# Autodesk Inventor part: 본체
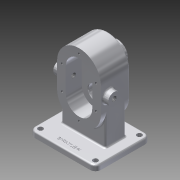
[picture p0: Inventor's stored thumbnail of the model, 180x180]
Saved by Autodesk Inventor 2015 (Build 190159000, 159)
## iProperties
Created: 2020-09
Part Number: 본체
Material: 알루미늄 6061
Document SubType Name: Modeling
Designer: Administrator
Density: 2.7 g/cm^3
Appearance: 알루미늄 - 평지
Mass: 1440.46 g
Surface Area: 785.636 cm^2
Volume: 533.505 cm^3
Author: Administrator
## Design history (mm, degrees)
sketch "스케치1"
  geometry: L1 (40, 0)-(40, 44); L2 (-40, 44)-(-40, 0); A1 r 40 centre (0, 0) between (-40, 0) and (40, 0); A2 r 40 centre (0, 44) between (40, 44) and (-40, 44); 1 further point
  constraints: 4 end point, 4 point on circle, 4 tangent, 2 centre point, 1 coincident, 1 parallel, 1 vertical
  dimensions: "d10" = 44 distance of L1.end L1.start; "d121" = 40 radius of A2
extrude "돌출1" new body sketch "스케치1" stored distance "d11" = 53; taper "d12" = 0 deg
sketch "스케치2"
  geometry: L1 (0, 0)-(0, 44); L2 (0, 0)-(0, 44); L3 (24, 0)-(24, 44); L4 (-24, 44)-(-24, 0); A1 r 24 centre (0, 0) between (-24, 0) and (24, 0); A2 r 24 centre (0, 44) between (24, 44) and (-24, 44); 1 further point
  constraints: 10 end point, 4 point on circle, 4 tangent, 2 centre point, 2 vertical, 1 midpoint, 1 parallel
  dimensions: "d13" = 44 distance of L1.start L1.end; "d14" = 48 diameter of A2
extrude "돌출2" cut sketch "스케치2" distance "d15" = 29; taper "d16" = 0 deg
sketch "스케치3"
  geometry: C1 r 19 at (0, 44); A1 r 40 centre (0, 44) between (40, 44) and (-40, 44) reference; 1 further point
  constraints: 1 centre point, 1 coincident
  dimensions: "d17" = 38 diameter of C1
extrude "돌출3" join sketch "스케치3" distance "d18" = 17; taper "d19" = 0 deg
sketch "스케치4"
  geometry: C1 r 19 at (0, 0) reference; C2 r 14 at (0, 0); 1 further point
  constraints: 1 centre point, 1 coincident
  dimensions: "d20" = 28 diameter of C2
extrude "돌출4" cut sketch "스케치4" distance "d21" = 7.3; taper "d22" = 0 deg
sketch "스케치5"
  geometry: C1 r 12.5 at (0, 44); A1 r 24 centre (0, 44) between (24, 44) and (-24, 44) reference; 1 further point
  constraints: 1 centre point, 1 coincident
  dimensions: "d23" = 25 diameter of C1
extrude "돌출5" cut sketch "스케치5" distance "d24" = 15; taper "d25" = 0 deg
sketch "스케치6"
  geometry: C1 r 12.5 at (0, 0) reference; C2 r 8.5 at (0, 0); 1 further point
  constraints: 1 centre point, 1 coincident
  dimensions: "d26" = 17 diameter of C2
extrude "돌출6" cut sketch "스케치6" distance "d27" = 20; taper "d28" = 0 deg
fillet "모깎기1" dims "d29" = 0.5
chamfer "모따기1" distance "d30" = 0.7; stored, may be unused: second distance "d31" = 2, angle "d32" = 30 deg
sketch "스케치7"
  geometry: C1 r 12.5 at (0, 0); A1 r 24 centre (0, 0) between (-24, 0) and (24, 0) reference; 1 further point
  constraints: 1 centre point, 1 coincident
  dimensions: "d33" = 25 diameter of C1
extrude "돌출7" cut sketch "스케치7" distance "d34" = 15; taper "d35" = 0 deg
chamfer "모따기2" distance "d36" = 1; stored, may be unused: second distance "d37" = 2, angle "d38" = 45 deg
sketch "스케치8"
  geometry: L1 (0, 0)-(0, 22); L2 (0, 44)-(0, 0) reference; L3 (0, 22)-(14, 22); C1 r 11 at (14, 22); 1 further point
  constraints: 4 end point, 1 centre point, 1 coincident, 1 horizontal, 1 midpoint
  dimensions: "d43" = 22 distance of L1.start L1.end (derived); "d44" = 14 distance of L1.end L3.end; "d45" = 22 diameter of C1
extrude "돌출8" join sketch "스케치8" distance "d46" = 10; taper "d47" = 0 deg
sketch "스케치9"
  geometry: L1 (0, 0)-(0, 22); L2 (0, 0)-(0, 44) reference; L3 (0, 22)-(-14, 22); C1 r 11 at (-14, 22); 1 further point
  constraints: 4 end point, 1 centre point, 1 coincident, 1 midpoint, 1 perpendicular
  dimensions: "d48" = 22 distance of L1.start L1.end (derived); "d49" = 14 distance of L1.end L3.end; "d50" = 22 diameter of C1
extrude "돌출9" join sketch "스케치9" distance "d51" = 10; taper "d52" = 0 deg
sketch "스케치10"
  geometry: C1 r 11 at (0, 0) reference; 1 further point
sketch "스케치11"
  geometry: C1 r 11 at (0, 0) reference; 1 further point
hole "구멍1" sketch "스케치11" at (0, 0) diameter "d53" = 8.376; stored, may be unused: countersink angle "d57" = 90 deg, drill point angle "d59" = 118 deg; dims "d54" = 26, "d55" = 4, "d56" = 2, "d58" = 30
hole "구멍2" sketch "스케치10" diameter "d60" = 8.376; stored, may be unused: countersink angle "d64" = 90 deg, drill point angle "d66" = 118 deg; dims "d61" = 26, "d62" = 4, "d63" = 2, "d65" = 30
fillet "모깎기2" dims "d67" = 3
sketch "스케치12"
  geometry: L1 (0, 44)-(0, 75); L2 (0, 44)-(-31, 44); L3 (0, 44)-(31, 44); C1 r 13.5 at (0, 44) reference; C2 r 2.828 at (0, 75); C3 r 2.236 at (31, 44); C4 r 2.236 at (-31, 44); A1 r 31 centre (0, 44) between (0, 75) and (-31, 44); 1 further point
  constraints: 6 end point, 4 centre point, 4 coincident, 3 point on circle, 2 horizontal, 1 vertical
  dimensions: "d68" = 62 diameter of A1; "d69" = 5.65685 diameter of C2; "d70" = 4.47214 diameter of C4; "d71" = 4.47214 diameter of C3
hole "구멍3" sketch "스케치12" at (0, 75), (31, 44), (-31, 44) diameter "d72" = 4.134; stored, may be unused: countersink angle "d76" = 90 deg, drill point angle "d78" = 118 deg; dims "d73" = 10, "d74" = 4, "d75" = 2, "d77" = 12
sketch "스케치13"
  geometry: L1 (0, 0)-(0, -31); L2 (0, 0)-(-31, 0); L3 (0, 0)-(31, 0); C1 r 13.5 at (0, 0) reference; C2 r 2.828 at (31, 0); C3 r 2.828 at (0, -31); C4 r 3.464 at (-31, 0); A1 r 31 centre (0, 0) between (0, -31) and (-31, 0); 1 further point
  constraints: 6 end point, 4 centre point, 4 coincident, 3 point on circle, 1 horizontal, 1 point on line, 1 vertical
  dimensions: "d79" = 62 diameter of A1; "d80" = 6.9282 diameter of C4; "d81" = 5.65685 diameter of C3; "d82" = 5.65685 diameter of C2
hole "구멍4" sketch "스케치13" at (31, 0), (-31, 0), (0, -31) diameter "d83" = 4.134; stored, may be unused: countersink angle "d87" = 90 deg, drill point angle "d89" = 118 deg; dims "d84" = 10, "d85" = 4, "d86" = 2, "d88" = 12
fillet "모깎기3" dims "d90" = 3
node "작업 평면1"
sketch "스케치15"
  geometry: L1 (0, 0)-(0, -43.5); L2 (0, 0)-(0, 56.5); L3 (0, 56.5)-(60, 56.5); L4 (60, 56.5)-(60, -43.5); L5 (60, -43.5)-(-60, -43.5); L6 (-60, -43.5)-(-60, 56.5); L7 (-60, 56.5)-(0, 56.5)
  constraints: 14 end point, 2 perpendicular, 2 vertical, 1 horizontal, 1 point on line
  dimensions: "d92" = 43.5 distance of L1.start L1.end; "d93" = 56.5 distance of L1.start L2.end; "d94" = 60 distance of L2.end L3.end; "d95" = 100 distance of L3.end L4.end; "d96" = 120 distance of L4.end L5.end; "d97" = 100 distance of L5.end L6.end
extrude "돌출10" join sketch "스케치15" distance "d98" = 10; taper "d99" = 0 deg
fillet "모깎기4" dims "d100" = 10
fillet "모깎기5" dims "d101" = 3
sketch "스케치16"
  geometry: L1 (-50, 40.5)-(50, 40.5) reference; L2 (-57, -46.5)-(-57, 33.5) reference; L3 (50, -53.5)-(-50, -53.5) reference; L4 (57, 33.5)-(57, -46.5) reference; C1 r 4.5 at (50, -46.5); C2 r 4.5 at (-50, -46.5); C3 r 4.5 at (-50, 33.5); C4 r 4.5 at (50, 33.5); A1 r 7 centre (50, 33.5) between (57, 33.5) and (50, 40.5) reference; A2 r 7 centre (-50, 33.5) between (-50, 40.5) and (-57, 33.5) reference; A3 r 7 centre (-50, -46.5) between (-57, -46.5) and (-50, -53.5) reference; A4 r 7 centre (50, -46.5) between (50, -53.5) and (57, -46.5) reference; 1 further point
  constraints: 4 centre point, 4 coincident
  dimensions: "d102" = 9 diameter of C1; "d103" = 9 diameter of C2; "d104" = 9 diameter of C3; "d105" = 9 diameter of C4
extrude "돌출11" cut sketch "스케치16" distance "d106" = 10; taper "d107" = 0 deg
sketch "스케치17"
  geometry: L1 (-50, -68)-(50, -68) reference; L2 (0, -68)-(0, -63.133); L3 (0, -63.133)-(-40, -63.133); L4 (0, -63.133)-(40, -63.133); L5 (-40, -63.133)-(-40, 0); L6 (40, -63.133)-(40, 0); A1 r 40 centre (0, 0) between (-40, 0) and (40, 0) reference; A2 r 41.127 centre (0, 9.56) between (-40, 0) and (40, 0); 1 further point
  constraints: 10 end point, 2 perpendicular, 2 point on circle, 1 centre point, 1 horizontal, 1 midpoint
  dimensions: "d108" = 40 distance of L2.end L3.end; "d109" = 40 distance of L2.end L4.end; "d110" = 4.86675 distance of L2.start L2.end; "d111" = 41.12653 radius of A2
extrude "돌출12" join sketch "스케치17" stored distance "d112" = 37; taper "d113" = 0 deg
fillet "모깎기6" dims "d114" = 3
fillet "모깎기7" dims "d115" = 3
sketch "스케치18"
  geometry: L1 (-50, -56.5)-(-60, -56.5); L2 (-60, -56.5)-(-60, -44.5); L3 (-60, -46.5)-(-60, 33.5) reference; L4 (-60, -44.5)-(0, -44.5); A1 r 10 centre (-50, -46.5) between (-60, -46.5) and (-50, -56.5) reference; 2 further points
  constraints: 6 end point, 1 coincident, 1 horizontal, 1 perpendicular, 1 point on line, 1 other
  dimensions: "d116" = 10 distance of L1.start L1.end; "d117" = 12 distance of L1.end L2.end; "d118" = 60 distance of L2.end L4.end
feature "엠보싱1" sketch "스케치18" dims "d10" = 44, "d119" = 0.5, "d120" = 0, "d121" = 40
node "솔리드1"
node "투영된 루프1"
other parameters: "d91" = -68
